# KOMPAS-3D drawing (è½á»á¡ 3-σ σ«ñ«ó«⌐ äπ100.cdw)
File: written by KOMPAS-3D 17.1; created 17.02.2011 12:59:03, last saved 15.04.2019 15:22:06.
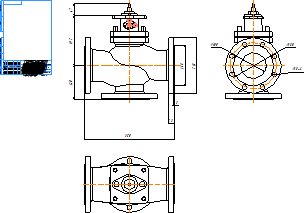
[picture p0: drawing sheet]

Title block, sheet 1: name: Клапан 3-х ходовой Ду100; material: Внимание! Данный продукт является объектом авторского права ООО «Торговый Дом АДЛ». / Запрещается изменение, копирование, распространение / (в том числе путем копирования на другие сайты и ресурсы в Интернете) / или любое иное использование информации и объектов без предварительного / согласия правообладателя (ООО «Торговый Дом АДЛ»).; scale: 1:1; sheets: 1; organisation: ООО "Торговый дом АДЛ"; sheet format: A4; stored path: \\adlc.lan\data\АДЛ_ПКД\3D-модели\ADL production\Клапаны ГРАНРЕГ\Трёхходовой клапан КМ307Ф\KOMPAS 2D\Клапан 3-х ходовой Ду100.cdw

Views: Спереди 1, Проекционный вид 2, Проекционный вид 3
Dimensions and other numbers on the sheet: 192; 130; 47; 350; 3; 23; 158; 215; 180; 18; 100; 1:1; 1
